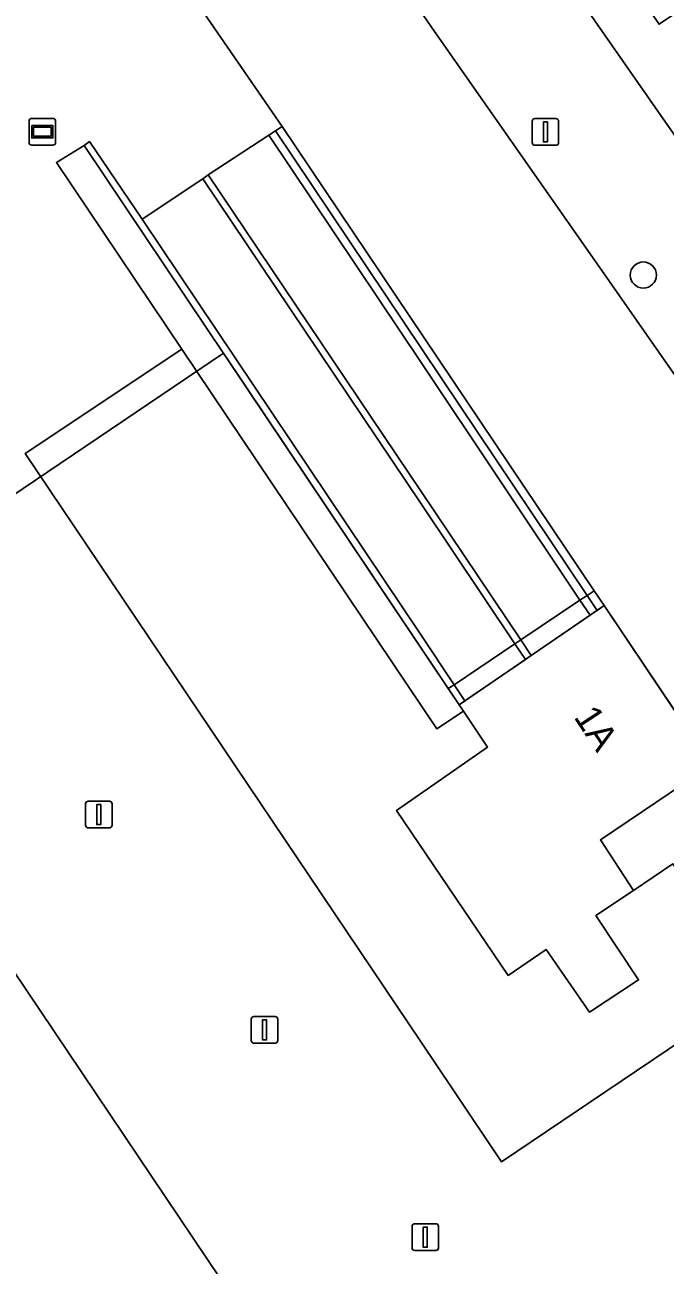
# Model space of a CAD drawing. Extents: x 161087 to 161926, y 382572 to 383873.
# Drawn here: x 161485.18 to 161509.14, y 382931.1 to 382977.51 of the extents above; entities that cross this region are included whole.
import ezdxf

# ---------------------------------------------------------------- set-up
doc = ezdxf.new("R2010")
doc.units = 0
for name, color, linetype in [('IMGEO_Boom', 7, 'Continuous'), ('IMGEO_Lichtmast', 7, 'Continuous'), ('IMGEO_Lijnafwatering', 7, 'Continuous'), ('IMGEO_Meer_plas_ven_vijver', 7, 'Continuous'), ('IMGEO_Muur', 7, 'Continuous'), ('IMGEO_Pand', 7, 'Continuous'), ('IMGEO_Pand_nummerreeks', 7, 'Continuous'), ('IMGEO_Pand_overbouw', 7, 'Continuous'), ('IMGEO_Rijbaan_lokaal_gesloten', 7, 'Continuous'), ('IMGEO_Voetgangersgebied_open', 7, 'Continuous'), ('IMGEO_Voetpad_open', 7, 'Continuous'), ('IMGEO_Wegwijzer', 7, 'Continuous')]:
    doc.layers.add(name, color=color, linetype=linetype)

msp = doc.modelspace()

# ---------------------------------------------------------------- linework, layer by layer
at = {"layer": 'IMGEO_Boom'}
msp.add_circle((161508.318, 382968.149), 0.489, dxfattribs=at)
at = {"layer": 'IMGEO_Lichtmast'}
for p, q in [((161504.159, 382973.104), (161504.159, 382973.904)), ((161504.159, 382973.904), (161504.159, 382973.104)), ((161504.259, 382974.004), (161505.049, 382974.004)), ((161505.049, 382974.004), (161504.259, 382974.004)), ((161505.149, 382973.904), (161505.149, 382973.104)), ((161505.149, 382973.104), (161505.149, 382973.904)), ((161505.049, 382973.004), (161504.259, 382973.004)), ((161504.259, 382973.004), (161505.049, 382973.004)), ((161487.449, 382947.564), (161487.449, 382948.364)), ((161487.449, 382948.364), (161487.449, 382947.564)), ((161487.549, 382948.464), (161488.339, 382948.464)), ((161488.339, 382948.464), (161487.549, 382948.464)), ((161488.439, 382948.364), (161488.439, 382947.564)), ((161488.439, 382947.564), (161488.439, 382948.364)), ((161488.339, 382947.464), (161487.549, 382947.464)), ((161487.549, 382947.464), (161488.339, 382947.464)), ((161493.75, 382940.406), (161494.54, 382940.406)), ((161494.54, 382940.406), (161493.75, 382940.406)), ((161493.65, 382939.506), (161493.65, 382940.306)), ((161493.65, 382940.306), (161493.65, 382939.506)), ((161494.64, 382940.306), (161494.64, 382939.506)), ((161494.64, 382939.506), (161494.64, 382940.306)), ((161494.54, 382939.406), (161493.75, 382939.406)), ((161493.75, 382939.406), (161494.54, 382939.406)), ((161499.663, 382931.751), (161499.663, 382932.551)), ((161499.663, 382932.551), (161499.663, 382931.751)), ((161499.763, 382932.651), (161500.553, 382932.651)), ((161500.553, 382932.651), (161499.763, 382932.651)), ((161500.653, 382932.551), (161500.653, 382931.751)), ((161500.653, 382931.751), (161500.653, 382932.551)), ((161500.553, 382931.651), (161499.763, 382931.651)), ((161499.763, 382931.651), (161500.553, 382931.651))]:
    msp.add_line(p, q, dxfattribs=at)
for points in [[(161504.579, 382973.879), (161504.729, 382973.879), (161504.729, 382973.129), (161504.579, 382973.129), (161504.579, 382973.879)], [(161487.869, 382948.339), (161488.019, 382948.339), (161488.019, 382947.589), (161487.869, 382947.589), (161487.869, 382948.339)], [(161494.07, 382940.281), (161494.22, 382940.281), (161494.22, 382939.531), (161494.07, 382939.531), (161494.07, 382940.281)], [(161500.083, 382932.526), (161500.233, 382932.526), (161500.233, 382931.776), (161500.083, 382931.776), (161500.083, 382932.526)]]:
    msp.add_lwpolyline(points, dxfattribs=at)
for centre, start, end in [((161504.259, 382973.904), 90, 180), ((161504.259, 382973.904), 90, 180), ((161505.049, 382973.904), 0, 90), ((161505.049, 382973.904), 360, 90), ((161504.259, 382973.104), 180, 270), ((161504.259, 382973.104), 180, 270), ((161505.049, 382973.104), 270, 0), ((161505.049, 382973.104), 270, 0), ((161487.549, 382948.364), 90, 180), ((161487.549, 382948.364), 90, 180), ((161488.339, 382948.364), 0, 90), ((161488.339, 382948.364), 360, 90), ((161487.549, 382947.564), 180, 270), ((161487.549, 382947.564), 180, 270), ((161488.339, 382947.564), 270, 0), ((161488.339, 382947.564), 270, 0), ((161493.75, 382940.306), 90, 180), ((161493.75, 382940.306), 90, 180), ((161494.54, 382940.306), 0, 90), ((161494.54, 382940.306), 360, 90), ((161493.75, 382939.506), 180, 270), ((161493.75, 382939.506), 180, 270), ((161494.54, 382939.506), 270, 0), ((161494.54, 382939.506), 270, 0), ((161499.763, 382932.551), 90, 180), ((161499.763, 382932.551), 90, 180), ((161500.553, 382932.551), 0, 90), ((161500.553, 382932.551), 360, 90), ((161499.763, 382931.751), 180, 270), ((161499.763, 382931.751), 180, 270), ((161500.553, 382931.751), 270, 0), ((161500.553, 382931.751), 270, 0)]:
    msp.add_arc(centre, 0.1, start, end, dxfattribs=at)
at = {"layer": 'IMGEO_Lijnafwatering'}
for points in [[(161506.585, 382968.563), (161500.511, 382977.259), (161494.985, 382985.288)], [(161519.31, 382950.344), (161506.585, 382968.563)]]:
    msp.add_lwpolyline(points, dxfattribs=at)
at = {"layer": 'IMGEO_Meer_plas_ven_vijver'}
msp.add_lwpolyline([(161501.584, 382951.836), (161500.596, 382951.167), (161491.048, 382965.377), (161485.192, 382961.474), (161500, 382939.449), (161503.013, 382934.968), (161512.58, 382941.413), (161509.426, 382946.113), (161507.956, 382945.121), (161506.546, 382944.183), (161508.138, 382941.774), (161506.298, 382940.572), (161504.684, 382942.912), (161503.262, 382941.947), (161499.082, 382948.109), (161502.491, 382950.485)], close=True, dxfattribs=at)
at = {"layer": 'IMGEO_Muur'}
for points in [[(161506.212, 382956.162), (161494.555, 382973.544), (161494.312, 382973.384), (161500, 382964.878), (161505.947, 382955.984)], [(161506.475, 382956.338), (161494.8, 382973.709), (161494.555, 382973.544), (161506.212, 382956.162)], [(161501.022, 382952.674), (161487.398, 382973.001), (161486.36, 382972.355), (161491.048, 382965.377), (161500.596, 382951.167), (161501.584, 382951.836), (161501.427, 382952.07)], [(161489.566, 382970.234), (161487.593, 382973.143), (161487.398, 382973.001), (161501.022, 382952.674), (161501.241, 382952.821), (161500, 382954.672)], [(161500, 382960.052), (161492.041, 382971.904), (161491.831, 382971.755), (161500, 382959.585), (161503.515, 382954.349), (161503.732, 382954.495)], [(161506.212, 382956.162), (161505.947, 382955.984), (161506.323, 382955.422), (161506.587, 382955.603)], [(161506.587, 382955.603), (161506.849, 382955.782), (161506.475, 382956.338), (161506.212, 382956.162)], [(161503.515, 382954.349), (161503.906, 382953.767), (161504.121, 382953.915), (161503.732, 382954.495)], [(161501.022, 382952.674), (161501.427, 382952.07), (161501.645, 382952.219), (161501.241, 382952.821)]]:
    msp.add_lwpolyline(points, close=True, dxfattribs=at)
at = {"layer": 'IMGEO_Pand'}
msp.add_lwpolyline([(161510.861, 382949.813), (161506.849, 382955.782), (161506.587, 382955.603), (161506.323, 382955.422), (161504.121, 382953.915), (161503.906, 382953.767), (161501.645, 382952.219), (161501.427, 382952.07), (161501.584, 382951.836), (161502.491, 382950.485), (161499.082, 382948.109), (161503.262, 382941.947), (161504.684, 382942.912), (161506.298, 382940.572), (161508.138, 382941.774), (161506.546, 382944.183), (161507.956, 382945.121), (161506.712, 382947.012)], close=True, dxfattribs=at)
at = {"layer": 'IMGEO_Pand_overbouw'}
msp.add_lwpolyline([(161492.605, 382965.232), (161429.792, 382922.791), (161453.212, 382885.739), (161522.217, 382932.918), (161506.849, 382955.782), (161501.427, 382952.07)], close=True, dxfattribs=at)
at = {"layer": 'IMGEO_Rijbaan_lokaal_gesloten'}
for points in [[(161505.947, 382955.984), (161500, 382964.878), (161494.312, 382973.384), (161492.041, 382971.904), (161500, 382960.052), (161503.732, 382954.495)], [(161491.831, 382971.755), (161489.566, 382970.234), (161500, 382954.672), (161501.241, 382952.821), (161503.515, 382954.349), (161500, 382959.585)], [(161505.947, 382955.984), (161503.732, 382954.495), (161504.121, 382953.915), (161506.323, 382955.422)], [(161501.241, 382952.821), (161501.645, 382952.219), (161503.906, 382953.767), (161503.515, 382954.349)]]:
    msp.add_lwpolyline(points, close=True, dxfattribs=at)
at = {"layer": 'IMGEO_Voetgangersgebied_open'}
for points in [[(161537.139, 382933.73), (161504.897, 382979.985), (161500.628, 382986.11), (161500, 382987.011), (161490.993, 382999.933), (161483.461, 383010.717), (161468.231, 383000.019), (161466.43, 382998.784), (161473.79, 382988.173), (161443.39, 382966.889), (161442.219, 382968.515), (161432.59, 382961.842), (161432.328, 382962.194), (161430.326, 382960.66), (161430.871, 382959.954), (161429.509, 382958.918), (161425.979, 382956.243), (161424.759, 382956.396), (161424.117, 382957.164), (161423.81, 382956.927)], [(161419.278, 382953.496), (161418.957, 382953.256), (161419.611, 382952.384), (161419.434, 382951.117), (161414.596, 382947.348), (161412.674, 382945.831), (161413.383, 382944.906), (161413.737, 382944.446), (161416.013, 382941.491), (161418.173, 382938.68), (161487.855, 382985.495), (161488.326, 382984.808), (161487.535, 382984.276), (161494.8, 382973.709), (161506.475, 382956.338), (161506.849, 382955.782), (161510.861, 382949.813), (161506.712, 382947.012), (161507.956, 382945.121), (161509.426, 382946.113)], [(161491.048, 382965.377), (161486.36, 382972.355), (161487.398, 382973.001), (161487.593, 382973.143), (161489.566, 382970.234), (161491.831, 382971.755), (161492.041, 382971.904), (161494.312, 382973.384), (161494.555, 382973.544), (161494.8, 382973.709), (161487.535, 382984.276), (161418.673, 382937.998), (161420.782, 382934.985), (161421.709, 382933.625), (161421.785, 382933.513), (161423.001, 382931.728), (161425.738, 382927.535), (161434.891, 382912.704), (161469.267, 382856.908), (161473.209, 382850.496), (161476.379, 382845.501)], [(161512.58, 382941.413), (161503.013, 382934.968), (161500, 382939.449), (161485.192, 382961.474), (161491.048, 382965.377)]]:
    msp.add_lwpolyline(points, dxfattribs=at)
for points in [[(161469.152, 382965.318), (161428.165, 382937.798), (161455.681, 382896.825), (161496.661, 382924.391)], [(161496.661, 382924.391), (161455.681, 382896.825), (161428.165, 382937.798), (161469.152, 382965.318)]]:
    msp.add_lwpolyline(points, close=True, dxfattribs=at)
at = {"layer": 'IMGEO_Voetpad_open'}
msp.add_lwpolyline([(161511.22, 382978.861), (161511.118, 382978.807), (161511.018, 382978.956), (161508.909, 382977.535), (161508.489, 382978.153), (161508.082, 382977.886), (161506.551, 382980.172), (161506.944, 382980.426), (161506.543, 382981.008), (161504.897, 382979.985), (161537.139, 382933.73), (161540.192, 382935.847), (161538.932, 382937.721), (161538.325, 382938.65), (161537.858, 382939.377), (161534.778, 382943.942), (161532.898, 382942.65), (161532.605, 382943.036), (161532.203, 382942.8), (161531.044, 382944.509), (161531.434, 382944.782), (161531.178, 382945.161), (161533.082, 382946.456)], close=True, dxfattribs=at)
at = {"layer": 'IMGEO_Wegwijzer'}
for p, q in [((161485.337, 382973.11), (161485.337, 382973.91)), ((161485.337, 382973.91), (161485.337, 382973.11)), ((161485.437, 382974.01), (161486.227, 382974.01)), ((161486.227, 382974.01), (161485.437, 382974.01)), ((161486.327, 382973.91), (161486.327, 382973.11)), ((161486.327, 382973.11), (161486.327, 382973.91)), ((161486.227, 382973.01), (161485.437, 382973.01)), ((161485.437, 382973.01), (161486.227, 382973.01))]:
    msp.add_line(p, q, dxfattribs=at)
for points in [[(161485.438, 382973.742), (161486.226, 382973.742), (161486.226, 382973.278), (161485.438, 382973.278), (161485.438, 382973.742)], [(161485.503, 382973.677), (161485.503, 382973.343), (161486.161, 382973.343), (161486.161, 382973.677), (161485.503, 382973.677)]]:
    msp.add_lwpolyline(points, dxfattribs=at)
for centre, start, end in [((161485.437, 382973.91), 90, 180), ((161485.437, 382973.91), 90, 180), ((161486.227, 382973.91), 0, 90), ((161486.227, 382973.91), 360, 90), ((161485.437, 382973.11), 180, 270), ((161485.437, 382973.11), 180, 270), ((161486.227, 382973.11), 270, 0), ((161486.227, 382973.11), 270, 0)]:
    msp.add_arc(centre, 0.1, start, end, dxfattribs=at)

# ---------------------------------------------------------------- texts
at = {"layer": 'IMGEO_Pand_nummerreeks'}
msp.add_text('1A', height=1, rotation=303.2944, dxfattribs=at).set_placement((161505.694, 382951.613))

doc.saveas('drawing.dxf')
